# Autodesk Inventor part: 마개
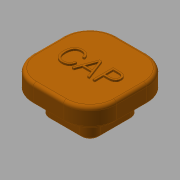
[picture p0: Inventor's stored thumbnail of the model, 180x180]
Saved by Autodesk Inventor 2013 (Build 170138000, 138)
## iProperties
Created: 2018-03
Part Number: 마개
Material: 고무
Document SubType Name: Modeling
Designer: mduedu
Density: 1 g/cm^3
Author: mduedu
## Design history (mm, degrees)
sketch "스케치1"
  geometry: L1 (12.5, 12.5)-(-12.5, 12.5); L2 (-12.5, 12.5)-(-12.5, -12.5); L3 (-12.5, -12.5)-(12.5, -12.5); L4 (12.5, -12.5)-(12.5, 12.5); L5 (12.5, 12.5)-(-12.5, -12.5); L6 (-12.5, 12.5)-(12.5, -12.5); 1 further point
  constraints: 12 end point, 2 midpoint, 2 parallel, 1 horizontal, 1 perpendicular
  dimensions: "d0" = 25 distance of L3.end L2.end; "d1" = 25 distance of L2.end L1.end
extrude "돌출1" new body sketch "스케치1" distance "d2" = 6; taper "d3" = 0 deg
fillet "모깎기1" dims "d4" = 8
fillet "모깎기2" dims "d5" = 1
sketch "스케치2"
  geometry: L1 (4.5, -12.5)-(-4.5, -12.5) reference; L2 (12.5, 4.5)-(12.5, -4.5) reference; L3 (-4.5, 12.5)-(4.5, 12.5) reference; L4 (-12.5, -4.5)-(-12.5, 4.5) reference; L5 (7.5, 4.5)-(7.5, -4.5); L6 (4.5, -7.5)-(-4.5, -7.5); L7 (-7.5, -4.5)-(-7.5, 4.5); L8 (-4.5, 7.5)-(4.5, 7.5); A1 r 8 centre (-4.5, -4.5) between (-12.5, -4.5) and (-4.5, -12.5) reference; A2 r 8 centre (4.5, -4.5) between (4.5, -12.5) and (12.5, -4.5) reference; A3 r 8 centre (4.5, 4.5) between (12.5, 4.5) and (4.5, 12.5) reference; A4 r 8 centre (-4.5, 4.5) between (-4.5, 12.5) and (-12.5, 4.5) reference; A5 r 3 centre (4.5, 4.5) between (7.5, 4.5) and (4.5, 7.5); A6 r 3 centre (4.5, -4.5) between (4.5, -7.5) and (7.5, -4.5); A7 r 3 centre (-4.5, -4.5) between (-7.5, -4.5) and (-4.5, -7.5); A8 r 3 centre (-4.5, 4.5) between (-4.5, 7.5) and (-7.5, 4.5); 1 further point
  constraints: 8 end point, 8 point on circle, 4 centre point, 7 other
  dimensions: "d6" = 5 distance between parallel lines of L8 L3
extrude "돌출2" join sketch "스케치2" distance "d7" = 6; taper "d8" = 0 deg
sketch "스케치3"
  geometry: L1 (4.5, 7.5)-(-4.5, 7.5) reference; L2 (-7.5, 4.5)-(-7.5, -4.5) reference; L3 (-4.5, -7.5)-(4.5, -7.5) reference; L4 (7.5, -4.5)-(7.5, 4.5) reference; L5 (-4.5, 5)-(4.5, 5); L6 (5, 4.5)-(5, -4.5); L7 (4.5, -5)-(-4.5, -5); L8 (-5, -4.5)-(-5, 4.5); A1 r 3 centre (4.5, 4.5) between (7.5, 4.5) and (4.5, 7.5) reference; A2 r 3 centre (-4.5, 4.5) between (-4.5, 7.5) and (-7.5, 4.5) reference; A3 r 3 centre (-4.5, -4.5) between (-7.5, -4.5) and (-4.5, -7.5) reference; A4 r 3 centre (4.5, -4.5) between (4.5, -7.5) and (7.5, -4.5) reference; A5 r 0.5 centre (4.5, 4.5) between (5, 4.5) and (4.5, 5); A6 r 0.5 centre (4.5, -4.5) between (4.5, -5) and (5, -4.5); A7 r 0.5 centre (-4.5, -4.5) between (-5, -4.5) and (-4.5, -5); A8 r 0.5 centre (-4.5, 4.5) between (-4.5, 5) and (-5, 4.5); 1 further point
  constraints: 8 end point, 8 point on circle, 4 centre point, 7 other
  dimensions: "d9" = 2.5 distance between parallel lines of L5 L1
extrude "돌출3" cut sketch "스케치3" stored distance "d10" = 10; taper "d11" = 0 deg
fillet "모깎기3" dims "d12" = 1
sketch "스케치4"
  geometry: L1 (7.5, 4.5)-(7.5, -4.5) reference; L2 (4.5, -7.5)-(-4.5, -7.5) reference; L3 (-7.5, -4.5)-(-7.5, 4.5) reference; L4 (-4.5, 7.5)-(4.5, 7.5) reference; L5 (4.5, -12.5)-(-4.5, -12.5) reference; L6 (12.5, 4.5)-(12.5, -4.5) reference; L7 (-4.5, 12.5)-(4.5, 12.5) reference; L8 (-12.5, -4.5)-(-12.5, 4.5) reference; L9 (11.5, 4.5)-(11.5, -4.5); L10 (4.5, -11.5)-(-4.5, -11.5); L11 (-11.5, -4.5)-(-11.5, 4.5); L12 (-4.5, 11.5)-(4.5, 11.5); A1 r 3 centre (4.5, -4.5) between (4.5, -7.5) and (7.5, -4.5) reference; A2 r 3 centre (-4.5, -4.5) between (-7.5, -4.5) and (-4.5, -7.5) reference; A3 r 3 centre (-4.5, 4.5) between (-4.5, 7.5) and (-7.5, 4.5) reference; A4 r 3 centre (4.5, 4.5) between (7.5, 4.5) and (4.5, 7.5) reference; A5 r 8 centre (-4.5, -4.5) between (-12.5, -4.5) and (-4.5, -12.5) reference; A6 r 8 centre (4.5, -4.5) between (4.5, -12.5) and (12.5, -4.5) reference; A7 r 8 centre (4.5, 4.5) between (12.5, 4.5) and (4.5, 12.5) reference; A8 r 8 centre (-4.5, 4.5) between (-4.5, 12.5) and (-12.5, 4.5) reference; A9 r 7 centre (4.5, 4.5) between (11.5, 4.5) and (4.5, 11.5); A10 r 7 centre (4.5, -4.5) between (4.5, -11.5) and (11.5, -4.5); A11 r 7 centre (-4.5, -4.5) between (-11.5, -4.5) and (-4.5, -11.5); A12 r 7 centre (-4.5, 4.5) between (-4.5, 11.5) and (-11.5, 4.5); 1 further point
  constraints: 8 end point, 8 point on circle, 4 centre point, 7 other
  dimensions: "d13" = 1 distance between parallel lines of L12 L7
extrude "돌출4" cut sketch "스케치4" distance "d14" = 1; taper "d15" = 0 deg
chamfer "모따기1" distance "d16" = 0.5; stored, may be unused: second distance "d17" = 2, angle "d18" = 45 deg
sketch "스케치5"
  geometry: 2 further points
  constraints: 1 coincident, 1 other
feature "엠보싱1" sketch "스케치5" dims "d0" = 25, "d1" = 25, "d19" = 0.5, "d20" = 0
node "솔리드1"
node "투영된 루프1"
node "투영된 루프2"
node "투영된 루프3"
